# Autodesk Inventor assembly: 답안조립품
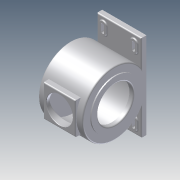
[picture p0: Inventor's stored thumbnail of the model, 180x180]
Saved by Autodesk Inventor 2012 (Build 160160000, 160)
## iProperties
Created: 2015-06
Part Number: 답안조립품
Document SubType Name: Assembly
Designer: User
Author: User
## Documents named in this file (2)
- C:\Documents and Settings\User\바탕 화면\450605V1016\답안조립품.iam
- C:\Documents and Settings\User\바탕 화면\450605V1016\본체.ipt
